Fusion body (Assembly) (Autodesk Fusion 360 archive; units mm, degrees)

design "Fusion body (Assembly)" references "KiCad pcb", "KiCad body"
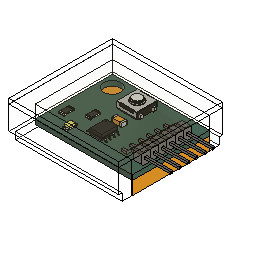
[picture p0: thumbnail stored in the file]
part number: 2026-03-04-14-55-37-115
component_insert "Component Insert1"
component_insert "Component Insert2"
sketch "Sketch1" plane through (0, -24.5, 0) normal (0, 1, 0) x axis (-1, 0, 0)
  line L1 (-100.9105, -1.787) -> (-68.5, -1.787)
  line L2 (-100.9105, -4) -> (-100.9105, -1.787)
  line L3 (-68.5, -4) -> (-100.9105, -4)
  line L4 (-68.5, -1.787) -> (-68.5, -4)
sketch "Sketch2" plane through (0, -24.5, 0) normal (0, 1, 0) x axis (-1, 0, 0)
sketch "Sketch3" plane through (0, 0, 0) normal (0, 1, 0) x axis (1, 0, 0)

design "KiCad body"
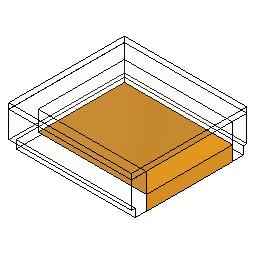
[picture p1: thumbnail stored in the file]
description: KiCad electronic assembly
part number: KiCad 1
description: Part Number
part number: KiCad_PCB
base_feature "Base Feature"
shell "Shell2" outerThickness 4
sketch "Sketch2" plane through (0, 0, 1.51) normal (0, 0, 1) x axis (-1, 0, 0)
  line L1 (-71.5, 51) -> (-101, 51)
  line L2 (-71.5, 27.5) -> (-71.5, 51)
  line L3 (-101, 27.5) -> (-71.5, 27.5)
  line L4 (-101, 51) -> (-101, 27.5)
  line L5 (-105, 55) -> (-67.5, 55)
  line L6 (-105, 23.5) -> (-105, 55)
  line L7 (-67.5, 23.5) -> (-105, 23.5)
  line L8 (-67.5, 55) -> (-67.5, 23.5)
  line L9 (-100.9105, 20.2399) -> (-100.9105, 56.324)
  perpendicular L7 L9
extrude "Extrude1" cut sketch "Sketch2" profile of L1 L3 L4 L5 L6 L7 L9 against normal blind 6.695
extrude "Extrude2" cut of existing geometry blind -2.01
extrude "Extrude3" cut of existing geometry blind -1.287
delete_face "DeleteFace2"
extrude "Extrude7" add of existing geometry blind 6.007
extrude "Extrude8" add of existing geometry blind 1.2
extrude "Extrude9" cut of existing geometry blind -1
extrude "Extrude10" cut of existing geometry blind -1
extrude "Extrude11" cut of existing geometry blind -1
shell "Shell3" innerThickness 1.62
extrude "Extrude4" add of existing geometry blind 8.886
extrude "Extrude5" cut of existing geometry blind -4.542
extrude "Extrude6" add of existing geometry blind 2.843
sketch "Sketch4" plane through (0, 0, 5.4) normal (0, 0, 1) x axis (-1, 0, 0)
  line L1 (-100.9105, 27.5) -> (-99.2905, 27.5)
  line L2 (-100.9105, 23.5) -> (-100.9105, 27.5)
  line L3 (-67.5, 23.5) -> (-100.9105, 23.5)
  line L4 (-67.5, 55) -> (-67.5, 23.5)
  line L5 (-100.9105, 55) -> (-67.5, 55)
  line L6 (-100.9105, 51) -> (-100.9105, 55)
  line L7 (-99.2905, 51) -> (-100.9105, 51)
  line L8 (-137.6211, 23.2339) -> (-104.1811, 23.2339)
  line L9 (-137.6211, 54.7339) -> (-137.6211, 23.2339)
  line L10 (-104.1811, 54.7339) -> (-137.6211, 54.7339)
  line L11 (-104.1811, 23.2339) -> (-104.1811, 54.7339)
  line L12 (-99.2905, 53.38) -> (-99.2905, 51)
  line L13 (-69.12, 53.38) -> (-99.2905, 53.38)
  line L14 (-69.12, 25.12) -> (-69.12, 53.38)
  line L15 (-99.2905, 25.12) -> (-69.12, 25.12)
  line L16 (-99.2905, 27.5) -> (-99.2905, 25.12)
  point P10 (-104.1811, 23.2339)
  point P13 (-104.1811, 54.7339)
  point P11 (-137.6211, 23.2339)
  horizontal L8
  vertical L9
  horizontal L10
  vertical L11
  dimension "d16" distance P10 P13 = 31.5
  dimension "d17" distance P10 P11 = 33.44
work_plane "WorkPlane1" AlongDistance 5.399
box_primitive "BoxPrimitive1" DistanceX 31.5 DistanceY 33.44 DistanceZ 1.5 OffsetDistanceX 0 OffsetDistanceY 0
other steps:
create_component "CreateComponent7"

design "KiCad pcb"
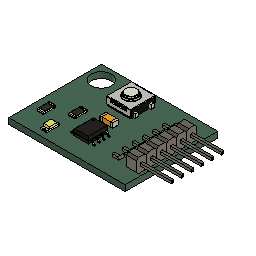
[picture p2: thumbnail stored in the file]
description: KiCad electronic assembly
part number: KiCad 1
description: Part Number
part number: Base
part number: Lead
part number: Body002
part number: Body003
part number: Body004
part number: Leads
part number: Button
part number: Package
part number: Body
base_feature "Base Feature1"
base_feature "Base Feature1"
base_feature "Base Feature1"
base_feature "Base Feature1"
base_feature "Base Feature1"
base_feature "Base Feature1"
base_feature "Base Feature1"
base_feature "Base Feature1"
base_feature "Base Feature1"
base_feature "Base Feature1"
base_feature "Base Feature1"
base_feature "Base Feature1"
base_feature "Base Feature1"
base_feature "Base Feature1"
base_feature "Base Feature1"
base_feature "Base Feature1"
base_feature "Base Feature1"
base_feature "Base Feature1"
base_feature "Base Feature1"
base_feature "Base Feature1"
base_feature "Base Feature1"
base_feature "Base Feature1"
base_feature "Base Feature1"
base_feature "Base Feature1"
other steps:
create_component "CreateComponent1"
create_component "CreateComponent1"
create_component "CreateComponent2"
create_component "CreateComponent1"
create_component "CreateComponent2"
create_component "CreateComponent3"
create_component "CreateComponent4"
create_component "CreateComponent3"
create_component "CreateComponent4"
create_component "CreateComponent2"
create_component "CreateComponent1"
create_component "CreateComponent2"
create_component "CreateComponent3"
create_component "CreateComponent1"
create_component "CreateComponent1"
create_component "CreateComponent2"
create_component "CreateComponent3"
create_component "CreateComponent4"
create_component "CreateComponent1"
create_component "CreateComponent2"
create_component "CreateComponent3"
create_component "CreateComponent5"
create_component "CreateComponent1"
create_component "CreateComponent2"
create_component "CreateComponent3"
create_component "CreateComponent4"
create_component "CreateComponent6"
create_component "CreateComponent1"
create_component "CreateComponent2"
create_component "CreateComponent3"
create_component "CreateComponent4"
create_component "CreateComponent7"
